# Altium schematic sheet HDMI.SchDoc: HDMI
size A4; Date: 01-DEC-2013; CompanyName: STMicroelectronics; Organization: Microcontrollers Division; Address1: 12, Rue Jules HOROWITZ; Address2: 38019 Grenoble; Address3: FRANCE; DocumentNumber: MB1272; Revision: A-01; SheetNumber: 9; SheetTotal: 15; Project: STM32MP15-DISCO PI
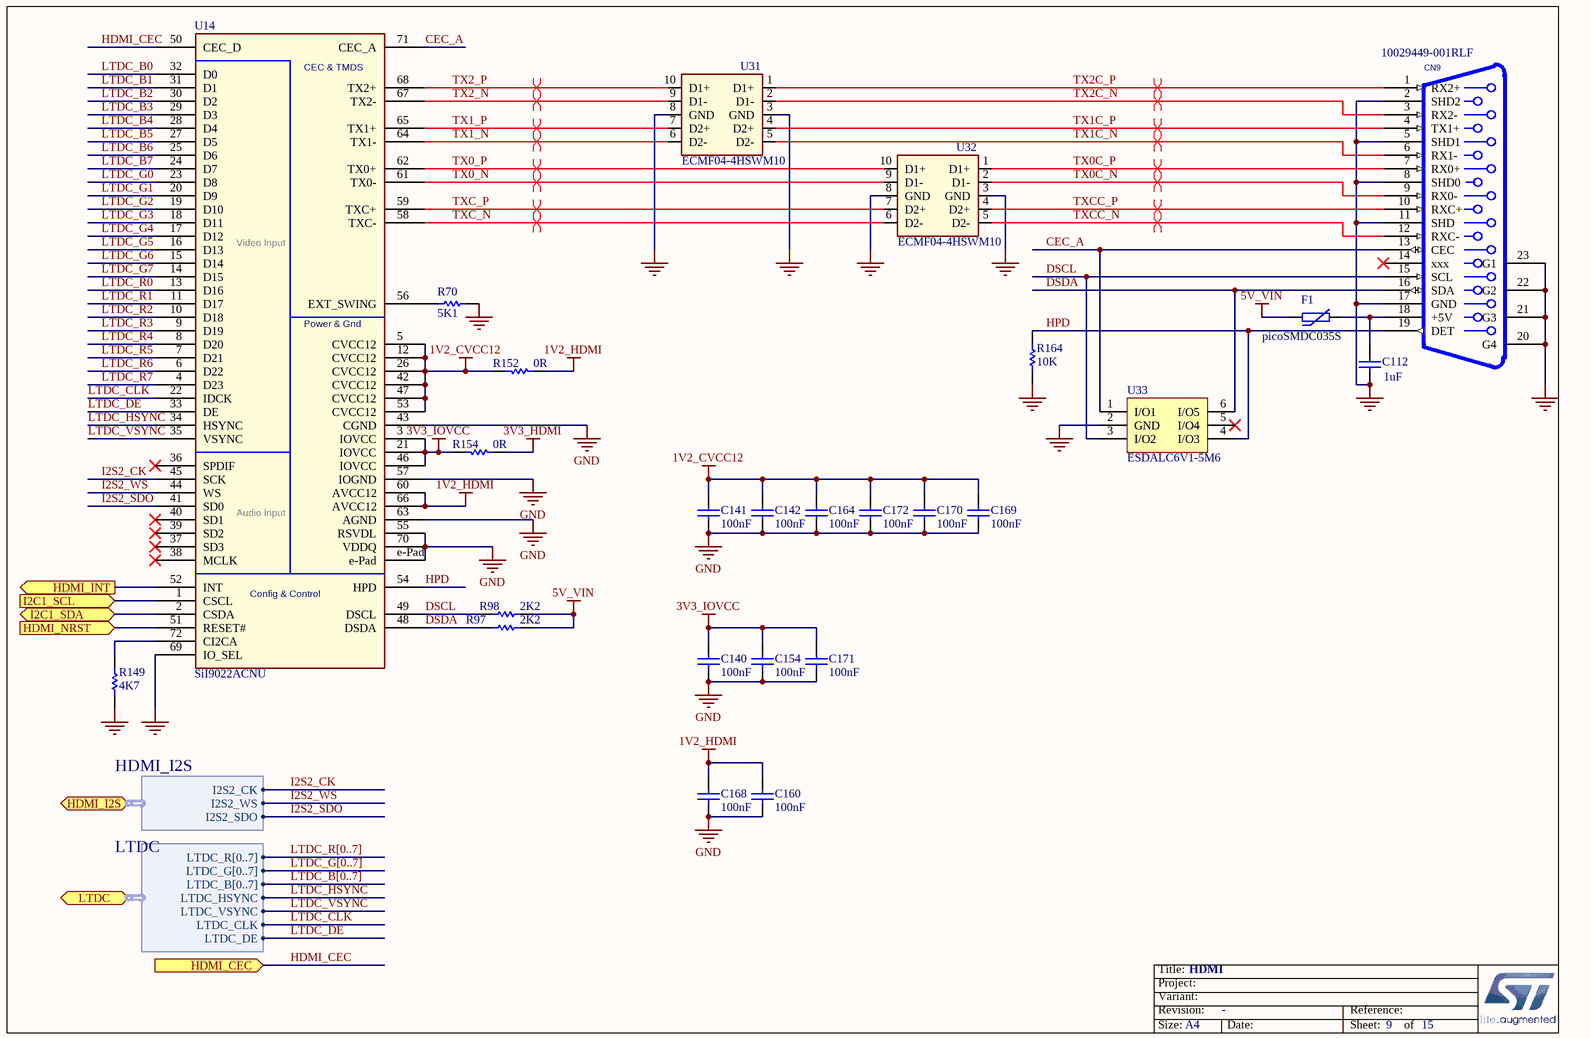
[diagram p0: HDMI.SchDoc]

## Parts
C112  value 1uF  [C0402]
C140  value 100nF  [C0402]
C141  value 100nF  [C0402]
C142  value 100nF  [C0402]
C154  value 100nF  [C0402]
C160  value 100nF  [C0402]
C164  value 100nF  [C0402]
C168  value 100nF  [C0402]
C169  value 100nF  [C0402]
C170  value 100nF  [C0402]
C171  value 100nF  [C0402]
C172  value 100nF  [C0402]
CN9  value 10029449-001RLF  [CON_HDMI_FCI-AMPHENOL_10029449-001RLF]
F1  value picoSMDC035S  [R0805]  (hidden comment: ​f)
R70  value 5K1  [R0402]
R97  value 2K2  [R0402]
R98  value 2K2  [R0402]
R149  value 4K7  [R0402]
R152  value 0R  [R0402]
R154  value 0R  [R0402]
R164  value 10K  [R0402]  (hidden comment: Resistor)
U14  value SiI9022ACNU  [ICC_QFN72-EPAD_10X10_P050]
U31  value ECMF04-4HSWM10  [ESD_UQFN-10L_2P60X1P35_P050]
U32  value ECMF04-4HSWM10  [ESD_UQFN-10L_2P60X1P35_P050]
U33  ESDALC6V1-5M6  [ESD_UQFN-6L_1P45X1_P050]

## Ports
HDMI_CEC (in), HDMI_I2S (harness HDMI_I2S), HDMI_INT (out), HDMI_NRST (in), I2C1_SCL (in), I2C1_SDA (bidir), LTDC (harness LTDC)

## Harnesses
LTDC: LTDC_R[0..7], LTDC_G[0..7], LTDC_B[0..7], LTDC_HSYNC, LTDC_VSYNC, LTDC_CLK, LTDC_DE
HDMI_I2S: I2S2_CK, I2S2_SDO, I2S2_WS

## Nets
1V2_CVCC12: C141.2 C142.2 C164.2 C169.2 C170.2 C172.2 R152.1 U14.5(CVCC12) U14.12(CVCC12) U14.26(CVCC12) U14.42(CVCC12) U14.47(CVCC12) U14.53(CVCC12)
1V2_HDMI: C160.2 C168.2 R152.2 U14.60(AVCC12) U14.66(AVCC12)
3V3_HDMI: R154.2
3V3_IOVCC: C140.2 C154.2 C171.2 R154.1 U14.3(IOVCC) U14.21(IOVCC) U14.46(IOVCC)
5V_VIN: F1.1 R97.2 R98.2
GND: C112.1 C140.1 C141.1 C142.1 C154.1 C160.1 C164.1 C168.1 C169.1 C170.1 C171.1 C172.1 CN9.2(SHD2) CN9.5(SHD1) CN9.8(SHD0) CN9.11(SHD) CN9.17(GND) CN9.20(G4) CN9.21(G3) CN9.22(G2) CN9.23(G1) R70.2 R149.1 R164.1 U14.43(CGND) U14.55(RSVDL) U14.57(IOGND) U14.63(AGND) U14.69(IO_SEL) U14.70(VDDQ) U14.e-Pad U31.3(GND) U31.8(GND) U32.3(GND) U32.8(GND) U33.2(GND)
CEC_A: CN9.13(CEC) U14.71(CEC_A) U33.1(I/O1)
DSCL: CN9.15(SCL) R98.1 U14.49(DSCL) U33.3(I/O2)
DSDA: CN9.16(SDA) R97.1 U14.48(DSDA) U33.6(I/O5)
HDMI_CEC: U14.50(CEC_D) ; port HDMI_CEC
HDMI_INT: U14.52(INT) ; port HDMI_INT
HDMI_NRST: U14.51(RESET#) ; port HDMI_NRST
HPD: CN9.19(DET) R164.2 U14.54(HPD) U33.4(I/O3)
I2C1_SCL: U14.1(CSCL) ; port I2C1_SCL
I2C1_SDA: U14.2(CSDA) ; port I2C1_SDA
I2S2_CK: U14.45(SCK) ; port HDMI_I2S.I2S2_CK
I2S2_SDO: U14.41(SD0) ; port HDMI_I2S.I2S2_SDO
I2S2_WS: U14.44(WS) ; port HDMI_I2S.I2S2_WS
LTDC_B0: U14.32(D0)
LTDC_B1: U14.31(D1)
LTDC_B2: U14.30(D2)
LTDC_B3: U14.29(D3)
LTDC_B4: U14.28(D4)
LTDC_B5: U14.27(D5)
LTDC_B6: U14.25(D6)
LTDC_B7: U14.24(D7)
LTDC_CLK: U14.22(IDCK) ; port LTDC.LTDC_CLK
LTDC_DE: U14.33(DE) ; port LTDC.LTDC_DE
LTDC_G0: U14.23(D8)
LTDC_G1: U14.20(D9)
LTDC_G2: U14.19(D10)
LTDC_G3: U14.18(D11)
LTDC_G4: U14.17(D12)
LTDC_G5: U14.16(D13)
LTDC_G6: U14.15(D14)
LTDC_G7: U14.14(D15)
LTDC_HSYNC: U14.34(HSYNC) ; port LTDC.LTDC_HSYNC
LTDC_R0: U14.13(D16)
LTDC_R1: U14.11(D17)
LTDC_R2: U14.10(D18)
LTDC_R3: U14.9(D19)
LTDC_R4: U14.8(D20)
LTDC_R5: U14.7(D21)
LTDC_R6: U14.6(D22)
LTDC_R7: U14.4(D23)
LTDC_VSYNC: U14.35(VSYNC) ; port LTDC.LTDC_VSYNC
TX0_N: U14.61(TX0-) U32.9(D1-)
TX0_P: U14.62(TX0+) U32.10(D1+)
TX0C_N: CN9.9(RX0-) U32.2(D1-)
TX0C_P: CN9.7(RX0+) U32.1(D1+)
TX1_N: U14.64(TX1-) U31.6(D2-)
TX1_P: U14.65(TX1+) U31.7(D2+)
TX1C_N: CN9.6(RX1-) U31.5(D2-)
TX1C_P: CN9.4(TX1+) U31.4(D2+)
TX2_N: U14.67(TX2-) U31.9(D1-)
TX2_P: U14.68(TX2+) U31.10(D1+)
TX2C_N: CN9.3(RX2-) U31.2(D1-)
TX2C_P: CN9.1(RX2+) U31.1(D1+)
TXC_N: U14.58(TXC-) U32.6(D2-)
TXC_P: U14.59(TXC+) U32.7(D2+)
TXCC_N: CN9.12(RXC-) U32.5(D2-)
TXCC_P: CN9.10(RXC+) U32.4(D2+)
NetC112_2: C112.2 CN9.18(+5V) F1.2
NetR70_1: R70.1 U14.56(EXT_SWING)
NetR149_2: R149.2 U14.72(CI2CA)

Not connected (* = marked no-connect by the designer): CN9 14(xxx)*; U14 36(SPDIF)* 37(SD3)* 38(MCLK)* 39(SD2)* 40(SD1)*; U33 5(I/O4)*

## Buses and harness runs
bus LTDC_B[0..7]
bus LTDC_G[0..7]
bus LTDC_R[0..7]

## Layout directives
differential pair: TX0_N, TX0_P, TX0C_N, TX0C_P, TX1_N, TX1_P, TX1C_N, TX1C_P, TX2_N, TX2_P, TX2C_N, TX2C_P, TXC_N, TXC_P, TXCC_N, TXCC_P

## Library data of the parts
C112 = MCD-00095: Capacitor,1uF,6V3,X5R,10%,0402; Manufacturer_Part_Number: GRM155R61E105KA12; Manufacturer: MURATA; Alternate_Manufacturer_Part_Number: GRM155R60J105KE19; ECCN_US: EAR99; ECCN_EU: NEC; Provided_By: SUBCO; Initial_Board_Reference: mb1262
C140-C142 C154 C160 C164 C168-C172 = MCD-00006: Capacitor,100nF,16V,X7R,10%,0402; Manufacturer_Part_Number: CC0402KRX7R7BB104; Manufacturer: YAGEO; Alternate_Manufacturer: MURATA; Alternate_Manufacturer_Part_Number: GCM155R71C104KA55D; Provided_By: SUBCO; Initial_Board_Reference: mb1274
CN9 = MCD-00307: HDMI Receptacle Type A 19pins standard Connector; Manufacturer: FCI; Provided_By: SUBCO; Initial_Board_Reference: MB1272
F1 = MCD-01133: Surface mount resettable polyswitch fuse.I hold=0.35A and I trigger=0.75A; Part_Type: Misc; Manufacturer: TE CONNECTIVITY; Provided_By: SUBCO; Initial_Board_Reference: MB1272
R70 = MCD-00333: Resistor,5K1,0402,1%,1/16W; Manufacturer_Part_Number: RC0402FR-075K1L; Manufacturer: YAGEO; Provided_By: SUBCO; Initial_Board_Reference: mb1272
R97 R98 = MCD-00057: Resistor,2K2,0402,1%,1/16W; Manufacturer_Part_Number: RC0402FR-072K2L; Manufacturer: YAGEO; Provided_By: SUBCO; Initial_Board_Reference: mb1274
R149 = MCD-00065: Resistor,4K7,0402,1%,1/16W; Manufacturer_Part_Number: RC0402FR-074K7L; Manufacturer: YAGEO; Alternate_Manufacturer_Part_Number: RT0402FRE074K7L; Provided_By: SUBCO; Initial_Board_Reference: mb1274
R152 R154 = MCD-00052: Resistor,0R,0402,5%,1/16W; Manufacturer_Part_Number: RC0402JR-070RL; Manufacturer: YAGEO; Provided_By: SUBCO; Initial_Board_Reference: mb1274
R164 = MCD-00053: Resistor,10K,0402,1%,1/16W; Manufacturer_Part_Number: RC0402FR-0710KL; Manufacturer: YAGEO; Provided_By: SUBCO; Initial_Board_Reference: MB1274
U14 = MCD-00267: HDMI Transmitter, 72-pin 10 × 10 mm QFN; Part_Type: IC; Manufacturer: LATTICE; Provided_By: SUBCO; Initial_Board_Reference: MB1272
U31 U32 = MCD-00297: ESD protection & Common Filter High Speed serial Interfaces; Part_Type: Diode; Manufacturer: STMICROELECTRONICS; BMS_Part_Number: 9151127; Provided_By: SUBCO with ST control; Initial_Board_Reference: MB1272
U33 = MCD-01457: ESD protection , 5 lines; Part_Type: Diode; Manufacturer: STMICROELECTRONICS; Provided_By: SUBCO; Initial_Board_Reference: MB1272B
